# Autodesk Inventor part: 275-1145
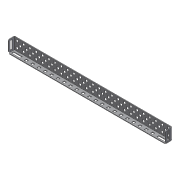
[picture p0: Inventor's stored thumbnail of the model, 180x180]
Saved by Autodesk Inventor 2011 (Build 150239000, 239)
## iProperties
Company: Autodesk Inc.
Created: 2005-08
Part Number: 275-1145
Document SubType Name: Sheet Metal
Designer: Autodesk Inc.
Density: 1 g/cm^3
Sheet Metal Rule: Default
Catalog Web Link: http://www.vexrobotics.com/rails.html
Description: This rail has holes on 0.500" increments and another row in-between. This part is an angle with one narrow and one taller side.
Vendor: Innovation First, Inc.
Author: Autodesk Inc.
Title: VEX Robotics Kit of Parts
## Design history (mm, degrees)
node "Face2"
  sketch "Sketch1"
    geometry: L1 (-157.48, 22.86)-(157.48, 22.86); L2 (-154.686, 19.939)-(-150.114, 19.939); L3 (-150.114, 19.939)-(-150.114, 15.367); L4 (-150.114, 15.367)-(-154.686, 15.367); L5 (-154.686, 15.367)-(-154.686, 19.939); L6 (-154.686, 7.239)-(-150.114, 7.239); L7 (-150.114, 7.239)-(-150.114, 2.667); L8 (-150.114, 2.667)-(-154.686, 2.667); L9 (-154.686, 2.667)-(-154.686, 7.239); L10 (-141.986, 19.939)-(-137.414, 19.939); L11 (-137.414, 19.939)-(-137.414, 15.367); L12 (-137.414, 15.367)-(-141.986, 15.367); L13 (-141.986, 15.367)-(-141.986, 19.939); L14 (-141.986, 7.239)-(-137.414, 7.239); L15 (-137.414, 7.239)-(-137.414, 2.667); L16 (-137.414, 2.667)-(-141.986, 2.667); L17 (-141.986, 2.667)-(-141.986, 7.239); L18 (-148.336, 9.017)-(-148.336, 13.589); L19 (-148.336, 13.589)-(-143.764, 13.589); L20 (-143.764, 9.017)-(-148.336, 9.017); L21 (-143.764, 13.589)-(-143.764, 9.017); L22 (-135.636, 9.017)-(-135.636, 13.589); L23 (-131.064, 9.017)-(-135.636, 9.017); L24 (-135.636, 13.589)-(-131.064, 13.589); L25 (-131.064, 13.589)-(-131.064, 9.017); L26 (-129.286, 15.367)-(-129.286, 19.939); L27 (-129.286, 2.667)-(-129.286, 7.239); L28 (-124.714, 2.667)-(-129.286, 2.667); L29 (-124.714, 7.239)-(-124.714, 2.667); L30 (-129.286, 7.239)-(-124.714, 7.239); L31 (-124.714, 15.367)-(-129.286, 15.367); L32 (-129.286, 19.939)-(-124.714, 19.939); L33 (-124.714, 19.939)-(-124.714, 15.367); L34 (-122.936, 9.017)-(-122.936, 13.589); L35 (-118.364, 9.017)-(-122.936, 9.017); L36 (-122.936, 13.589)-(-118.364, 13.589); L37 (-118.364, 13.589)-(-118.364, 9.017); L38 (-116.586, 15.367)-(-116.586, 19.939); L39 (-116.586, 2.667)-(-116.586, 7.239); L40 (-112.014, 2.667)-(-116.586, 2.667); L41 (-112.014, 7.239)-(-112.014, 2.667); L42 (-116.586, 7.239)-(-112.014, 7.239); L43 (-112.014, 15.367)-(-116.586, 15.367); L44 (-116.586, 19.939)-(-112.014, 19.939); L45 (-112.014, 19.939)-(-112.014, 15.367); L46 (-110.236, 9.017)-(-110.236, 13.589); L47 (-105.664, 9.017)-(-110.236, 9.017); L48 (-110.236, 13.589)-(-105.664, 13.589); L49 (-105.664, 13.589)-(-105.664, 9.017); L50 (-103.886, 15.367)-(-103.886, 19.939); L51 (-103.886, 2.667)-(-103.886, 7.239); L52 (-99.314, 2.667)-(-103.886, 2.667); L53 (-99.314, 7.239)-(-99.314, 2.667); L54 (-103.886, 7.239)-(-99.314, 7.239); L55 (-99.314, 15.367)-(-103.886, 15.367); L56 (-103.886, 19.939)-(-99.314, 19.939); L57 (-99.314, 19.939)-(-99.314, 15.367); L58 (-97.536, 9.017)-(-97.536, 13.589); L59 (-92.964, 9.017)-(-97.536, 9.017); L60 (-97.536, 13.589)-(-92.964, 13.589); L61 (-92.964, 13.589)-(-92.964, 9.017); L62 (-91.186, 15.367)-(-91.186, 19.939); L63 (-91.186, 2.667)-(-91.186, 7.239); L64 (-86.614, 2.667)-(-91.186, 2.667)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; 2 further points
    constraints: 600 end point, 12 parallel, 8 collinear, 7 horizontal, 6 perpendicular, 1 coincident, 1 midpoint, 552 other
    dimensions: "d20" = 2.794 distance between parallel lines of L192 L5; "d22" = 2.921 distance between parallel lines of L1 L2; "d23" = 22.86 distance between parallel lines of L191 L1; "d24" = 4.572 distance of L4.end L2.start; "d25" = 8.128 distance between parallel lines of L6 L4; "d26" = 4.572 distance of L8.end L6.start; "d125" = 314.96 distance of L190.end L191.end; "d126" = 4.572 distance of L2.start L2.end; "d127" = 4.572 distance of L18.end L19.end; "d128" = 4.572 distance of L19.end L20.start; "d129" = 9.017 distance between parallel lines of L191 L20; "d130" = 9.144 distance between parallel lines of L192 L18; "d133" = 15.494 distance between parallel lines of L192 L13; "d134" = 4.572 distance of L10.start L10.end; "d139" = 2.794 distance between parallel lines of L190 L300
node "Flange5"
node "Flange6"
feature "Corner Chamfer2" dims "d84" = 1.905, "d85" = 6.35, angle "d86" = 45 deg
node "Flange7"
sketch "Sketch11" dims "d99" = 25.4
  geometry: L1 (314.579, -9.246)-(314.579, 0) reference; L2 (-0.381, 0)-(-0.381, -9.246) reference; L3 (1.524, -11.151)-(312.674, -11.151) reference; L4 (2.413, -3.785)-(19.685, -3.785); L5 (19.685, -3.785)-(19.685, -8.357); L6 (19.685, -8.357)-(2.413, -8.357); L7 (2.413, -8.357)-(2.413, -3.785); L8 (27.813, -3.785)-(32.385, -3.785); L9 (32.385, -3.785)-(32.385, -8.357); L10 (32.385, -8.357)-(27.813, -8.357); L11 (27.813, -8.357)-(27.813, -3.785); L12 (40.513, -8.357)-(40.513, -3.785); L13 (45.085, -8.357)-(40.513, -8.357); L14 (45.085, -3.785)-(45.085, -8.357); L15 (40.513, -3.785)-(45.085, -3.785); L16 (53.213, -8.357)-(53.213, -3.785); L17 (57.785, -8.357)-(53.213, -8.357); L18 (57.785, -3.785)-(57.785, -8.357); L19 (53.213, -3.785)-(57.785, -3.785); L20 (65.913, -8.357)-(65.913, -3.785); L21 (70.485, -8.357)-(65.913, -8.357); L22 (70.485, -3.785)-(70.485, -8.357); L23 (65.913, -3.785)-(70.485, -3.785); L24 (78.613, -8.357)-(78.613, -3.785); L25 (83.185, -8.357)-(78.613, -8.357); L26 (83.185, -3.785)-(83.185, -8.357); L27 (78.613, -3.785)-(83.185, -3.785); L28 (91.313, -8.357)-(91.313, -3.785); L29 (95.885, -8.357)-(91.313, -8.357); L30 (95.885, -3.785)-(95.885, -8.357); L31 (91.313, -3.785)-(95.885, -3.785); L32 (104.013, -8.357)-(104.013, -3.785); L33 (108.585, -8.357)-(104.013, -8.357); L34 (108.585, -3.785)-(108.585, -8.357); L35 (104.013, -3.785)-(108.585, -3.785); L36 (116.713, -8.357)-(116.713, -3.785); L37 (121.285, -8.357)-(116.713, -8.357); L38 (121.285, -3.785)-(121.285, -8.357); L39 (116.713, -3.785)-(121.285, -3.785); L40 (129.413, -8.357)-(129.413, -3.785); L41 (133.985, -8.357)-(129.413, -8.357); L42 (133.985, -3.785)-(133.985, -8.357); L43 (129.413, -3.785)-(133.985, -3.785); L44 (142.113, -8.357)-(142.113, -3.785); L45 (146.685, -8.357)-(142.113, -8.357); L46 (146.685, -3.785)-(146.685, -8.357); L47 (142.113, -3.785)-(146.685, -3.785); L48 (154.813, -8.357)-(154.813, -3.785); L49 (159.385, -8.357)-(154.813, -8.357); L50 (159.385, -3.785)-(159.385, -8.357); L51 (154.813, -3.785)-(159.385, -3.785); L52 (167.513, -8.357)-(167.513, -3.785); L53 (172.085, -8.357)-(167.513, -8.357); L54 (172.085, -3.785)-(172.085, -8.357); L55 (167.513, -3.785)-(172.085, -3.785); L56 (294.513, -3.785)-(311.785, -3.785); L57 (311.785, -3.785)-(311.785, -8.357); L58 (311.785, -8.357)-(294.513, -8.357); L59 (294.513, -8.357)-(294.513, -3.785); L60 (180.213, -8.357)-(180.213, -3.785); L61 (184.785, -8.357)-(180.213, -8.357); L62 (184.785, -3.785)-(184.785, -8.357); L63 (180.213, -3.785)-(184.785, -3.785); L64 (192.913, -8.357)-(192.913, -3.785)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
  constraints: 184 end point, 6 parallel, 4 horizontal, 3 perpendicular, 2 collinear, 160 other
  dimensions: "d88" = 17.272 distance between parallel lines of L5 L7; "d89" = 2.794 distance between parallel lines of L3 L6; "d90" = 2.794 distance between parallel lines of L2 L7; "d91" = 4.572 distance between parallel lines of L4 L6; "d92" = 4.572 distance between parallel lines of L9 L11; "d93" = 8.128 distance between parallel lines of L11 L5; "d96" = 12.7 distance of L10.end L12.start; "d103" = 2.794 distance between parallel lines of L1 L57; "d111" = 4.572 distance between parallel lines of L56 L58; "d112" = 2.794 distance between parallel lines of L3 L58; "d138" = 8.128 distance between parallel lines of L94 L59
cut "Cut2" sketch "Sketch11" dims "d113" = 1.27 (= Thickness), "d114" = 0
feature "Corner Chamfer3" dims "d115" = 1.905, "d116" = 6.35, angle "d117" = 45 deg
sketch "Sketch13"
  geometry: L1 (-9.246, 22.479)-(0, 22.479) reference; L2 (-11.151, 1.905)-(-11.151, 20.574) reference; L3 (-8.357, 19.685)-(-3.785, 19.685); L4 (-3.785, 19.685)-(-3.785, 2.413); L5 (-3.785, 2.413)-(-8.357, 2.413); L6 (-8.357, 2.413)-(-8.357, 19.685)
  constraints: 8 end point, 2 parallel, 1 horizontal, 1 perpendicular
  dimensions: "d118" = 2.794 distance between parallel lines of L2 L6; "d119" = 2.794 distance between parallel lines of L3 L1; "d121" = 17.272 distance of L5.end L3.start; "d122" = 4.572 distance of L3.start L3.end
cut "Cut3" sketch "Sketch13" dims "d123" = 1.27 (= Thickness), "d124" = 0
body "Solid1"
sketch "Sketch7"
  geometry: L1 (314.96, 0)-(314.96, 11.532); L2 (314.96, 11.532)-(0, 11.532); 2 other entities
  constraints: 4 end point, 4 other
face "Plate6" dims "d64" = 1.27 (= BendReliefWidth), "d65" = 0.635 (= BendReliefDepth), "d66" = 2.54 (= MinimumRemnant), "d67" = 0.381 (= BendRadius), "d68" = 11.5316, "d69" = 90 deg, "d70" = 0.381 (= BendRadius), "SeamGap" = 0.00508, "Thickness" = 1.27
bend "Bend5" dims "d64" = 1.27 (= BendReliefWidth), "d65" = 0.635 (= BendReliefDepth), "d66" = 2.54 (= MinimumRemnant), "d67" = 0.381 (= BendRadius), "d68" = 11.5316, "d69" = 90 deg, "d70" = 0.381 (= BendRadius), "SeamGap" = 0.00508, "Thickness" = 1.27
sketch "Sketch8"
  geometry: L1 (22.479, 0)-(22.479, 11.532); L2 (22.479, 11.532)-(0, 11.532); 2 other entities
  constraints: 4 end point, 4 other
face "Plate7" dims "d71" = 1.27 (= BendReliefWidth), "d72" = 0.635 (= BendReliefDepth), "d73" = 2.54 (= MinimumRemnant), "d74" = 0.381 (= BendRadius), "d75" = 11.5316, "d76" = 90 deg, "d77" = 0.381 (= BendRadius), "SeamGap" = 0.00508, "Thickness" = 1.27
bend "Bend6" dims "d71" = 1.27 (= BendReliefWidth), "d72" = 0.635 (= BendReliefDepth), "d73" = 2.54 (= MinimumRemnant), "d74" = 0.381 (= BendRadius), "d75" = 11.5316, "d76" = 90 deg, "d77" = 0.381 (= BendRadius), "SeamGap" = 0.00508, "Thickness" = 1.27
sketch "Sketch12"
  geometry: L1 (22.479, 0)-(22.479, 11.532); L2 (22.479, 11.532)-(0, 11.532); 2 other entities
  constraints: 4 end point, 4 other
face "Plate8" dims "d104" = 1.27 (= BendReliefWidth), "d105" = 0.635 (= BendReliefDepth), "d106" = 2.54 (= MinimumRemnant), "d107" = 0.381 (= BendRadius), "d108" = 11.5316, "d109" = 90 deg, "d110" = 0.381 (= BendRadius), "SeamGap" = 0.00508, "Thickness" = 1.27
bend "Bend7" dims "d104" = 1.27 (= BendReliefWidth), "d105" = 0.635 (= BendReliefDepth), "d106" = 2.54 (= MinimumRemnant), "d107" = 0.381 (= BendRadius), "d108" = 11.5316, "d109" = 90 deg, "d110" = 0.381 (= BendRadius), "SeamGap" = 0.00508, "Thickness" = 1.27
face "Plate9" dims "Thickness" = 1.27
other parameters: "BendRadius" = 0.381, "BendReliefWidth" = 1.27 (= Thickness), "BendReliefDepth" = 0.635 (= 0.5 x Thickness), "CornerReliefSize" = 5.08 (= 4 x Thickness), "MinimumRemnant" = 2.54 (= 2 x Thickness), "TransitionRadius" = 0.381 (= BendRadius), "d13" = 12.7, "d16" = 25.4, "d27" = 0.381 (= BendRadius), "JacobiRadiusSize" = 1.27 (= Thickness), "GapSize" = 1.27 (= Thickness), "d136" = 0.381 (= BendRadius)
